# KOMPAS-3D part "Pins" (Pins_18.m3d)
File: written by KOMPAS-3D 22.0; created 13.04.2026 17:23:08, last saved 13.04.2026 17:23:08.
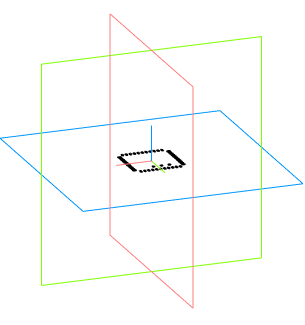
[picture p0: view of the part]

Document properties: Автор: Andrey; Полное имя файла: C:\Users\User1\Documents\Pins_18.m3d

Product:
- Part/product: Pins

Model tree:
1. Операция без истории:1
2. Операция без истории:2
3. Операция без истории:3
4. Операция без истории:4
5. Операция без истории:5
6. Операция без истории:6
7. Операция без истории:7
8. Операция без истории:8
9. Операция без истории:9
10. Операция без истории:10
11. Операция без истории:11
12. Операция без истории:12
13. Операция без истории:13
14. Операция без истории:14
15. Операция без истории:15
16. Операция без истории:16
17. Операция без истории:17
18. Операция без истории:18
19. Операция без истории:19
20. Операция без истории:20
21. Операция без истории:21
22. Операция без истории:22
23. Операция без истории:23
24. Операция без истории:24
25. Операция без истории:25
26. Операция без истории:26
27. Операция без истории:27
28. Операция без истории:28
29. Операция без истории:29
30. Операция без истории:30
31. Операция без истории:31
32. Операция без истории:32
33. Операция без истории:33
34. Операция без истории:34
35. Операция без истории:35
36. Операция без истории:36
37. Операция без истории:37
38. Операция без истории:38
39. Операция без истории:39
40. Операция без истории:40
41. Операция без истории:41
42. Операция без истории:42
43. Операция без истории:43
44. Операция без истории:44
45. Операция без истории:45
46. Операция без истории:46
47. Операция без истории:47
